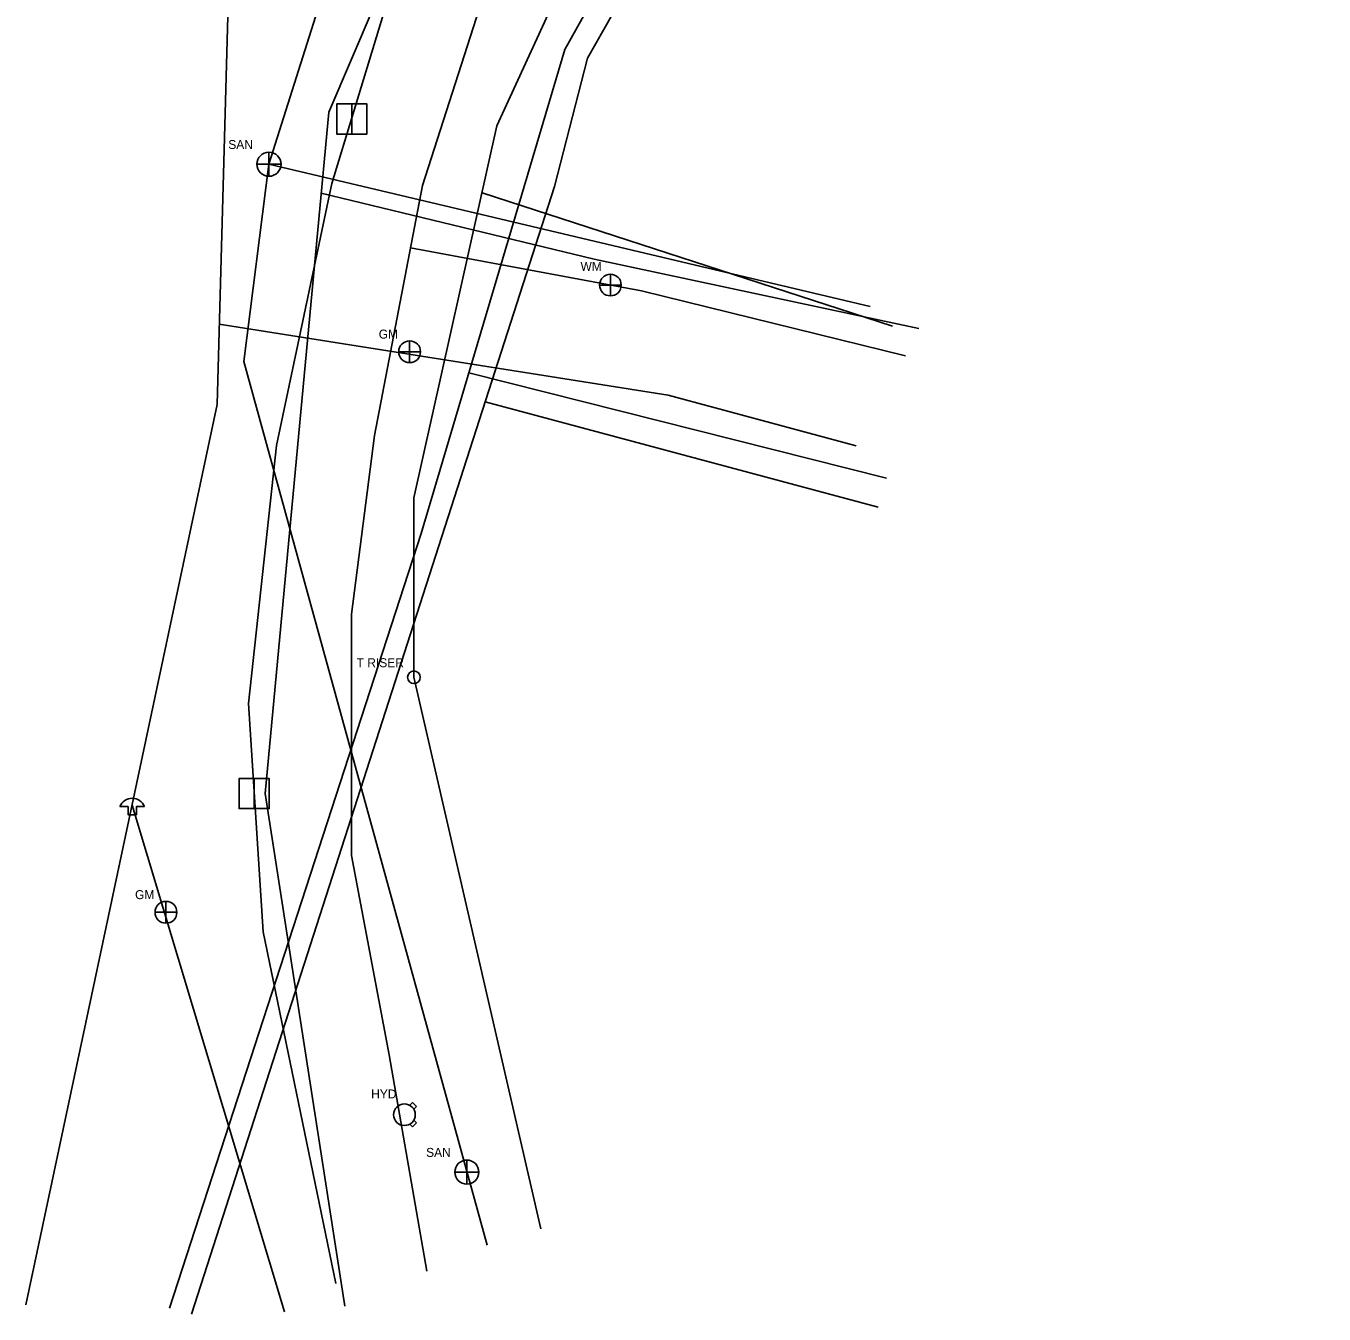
# Model space of a CAD drawing. Extents: x 551158 to 552108, y 1042267 to 1044064.
# Drawn here: x 551202 to 552108, y 1042267 to 1043165 of the extents above; entities that cross this region are included whole.
import ezdxf

# ---------------------------------------------------------------- set-up
doc = ezdxf.new("R2010")
doc.units = 0
for name, color, linetype in [('Common-Removals', 7, 'Continuous'), ('Utility-Cable', 7, 'Continuous'), ('Utility-Gas', 7, 'Continuous'), ('Utility-Pole', 7, 'Continuous'), ('Utility-Power', 7, 'Continuous'), ('Utility-Sanitary sewer', 7, 'Continuous'), ('Utility-Telephone', 7, 'Continuous'), ('Utility-Water', 7, 'Continuous')]:
    doc.layers.add(name, color=color, linetype=linetype)

msp = doc.modelspace()

# ---------------------------------------------------------------- linework, layer by layer
at = {"layer": 'Common-Removals'}
msp.add_line((551520.26, 1043049), (551806.58, 1042956.02), dxfattribs=at)
for points in [[(551418.21, 1042288.18), (551367.62, 1042533.64), (551357.31, 1042692.91), (551376.99, 1042872.8), (551415.4, 1043055.49), (551462.25, 1043209.14), (551535.32, 1043370.28), (551605.59, 1043490.2), (551705.83, 1043624.17), (551808.89, 1043763.77), (551899.77, 1043870.57), (552006.57, 1044001.74)], [(551561.23, 1042326.51), (551472.71, 1042711.13), (551472.71, 1042836.28), (551530.71, 1043095.75), (551631.44, 1043315.53), (551781.02, 1043556.68), (551942.8, 1043752.05), (552107.64, 1043938.25)]]:
    msp.add_lwpolyline(points, dxfattribs=at)
at = {"layer": 'Utility-Cable'}
msp.add_line((551510.99, 1042923.37), (551802.4, 1042849.99), dxfattribs=at)
msp.add_lwpolyline([(551302.24, 1042271), (551477.71, 1042811.45), (551578.06, 1043148.89), (551722.69, 1043407.88), (551880.78, 1043952.78), (551948.05, 1044063.78)], dxfattribs=at)
at = {"layer": 'Utility-Gas'}
for p, q in [((551469.82, 1042938.16), (551462.21, 1042938.16)), ((551469.77, 1042945.77), (551469.77, 1042938.16)), ((551469.77, 1042938.16), (551469.77, 1042938.16)), ((551469.77, 1042938.16), (551477.38, 1042938.16)), ((551469.77, 1042938.16), (551469.77, 1042930.6)), ((551276.1, 1042621.84), (551382.51, 1042268.41)), ((551299.79, 1042554.8), (551299.79, 1042547.19)), ((551299.84, 1042547.19), (551292.23, 1042547.19)), ((551299.79, 1042547.19), (551299.79, 1042547.19)), ((551299.79, 1042547.19), (551307.41, 1042547.19)), ((551299.79, 1042547.19), (551299.79, 1042539.63))]:
    msp.add_line(p, q, dxfattribs=at)
for points in [[(551883.28, 1044046.83), (551543.2, 1043513.97), (551342.83, 1043172.29), (551335.46, 1042901.45), (551202.12, 1042273.42)], [(551336.99, 1042957.33), (551650.09, 1042907.88), (551781.23, 1042872.53)], [(551267.69, 1042620.96), (551273.4, 1042620.96), (551273.4, 1042615.25), (551279.12, 1042615.25), (551279.12, 1042620.96), (551284.83, 1042620.96)]]:
    msp.add_lwpolyline(points, dxfattribs=at)
for centre in [(551469.77, 1042938.16), (551299.79, 1042547.19)]:
    msp.add_circle(centre, 7.61, dxfattribs=at)
for centre, radius, start, end in [((551469.77, 1042938.16), 7.61, 0.00229, 90.00084), ((551276.26, 1042617.4), 9.28, 22.56866, 157.43134), ((551299.79, 1042547.19), 7.61, 0.00229, 90.00084)]:
    msp.add_arc(centre, radius, start, end, dxfattribs=at)
at = {"layer": 'Utility-Pole'}
for points in [[(551418.98, 1043090.02), (551429.48, 1043090.02), (551429.48, 1043111.03), (551418.98, 1043111.03)], [(551418.98, 1043111.03), (551439.99, 1043111.03), (551439.99, 1043090.02), (551418.98, 1043090.02)], [(551350.8, 1042619.47), (551361.3, 1042619.47), (551361.3, 1042640.47), (551350.8, 1042640.47)], [(551350.8, 1042640.47), (551371.8, 1042640.47), (551371.8, 1042619.47), (551350.8, 1042619.47)]]:
    msp.add_lwpolyline(points, close=True, dxfattribs=at)
at = {"layer": 'Utility-Power'}
for points in [[(551985.8, 1044024.18), (551789, 1043787.2), (551589.43, 1043516.95), (551413.43, 1043105.33), (551369.08, 1042629.97), (551424.51, 1042272.41)], [(551408.16, 1043048.87), (551598.51, 1043002.84), (551824.9, 1042954.32)]]:
    msp.add_lwpolyline(points, dxfattribs=at)
at = {"layer": 'Utility-Sanitary sewer'}
for p, q in [((551371.64, 1043060.66), (551371.64, 1043077.36)), ((551363.34, 1043068.96), (551380.04, 1043068.96)), ((551791.14, 1042969.79), (551371.64, 1043069.06)), ((551371.64, 1043068.96), (551371.64, 1043068.96)), ((551509.66, 1042357.68), (551509.66, 1042374.39)), ((551501.36, 1042365.99), (551518.06, 1042365.99)), ((551509.66, 1042365.99), (551509.66, 1042365.99))]:
    msp.add_line(p, q, dxfattribs=at)
msp.add_lwpolyline([(551523.75, 1042314.92), (551354.03, 1042931.36), (551371.64, 1043069.06), (551430.88, 1043256.39), (551502.93, 1043406.9), (551815.16, 1043631.06), (552080.95, 1043954.5)], dxfattribs=at)
for centre in [(551371.64, 1043068.96), (551509.66, 1042365.98)]:
    msp.add_circle(centre, 8.4, dxfattribs=at)
at = {"layer": 'Utility-Telephone'}
msp.add_line((551522.43, 1042903.3), (551796.62, 1042829.74), dxfattribs=at)
msp.add_lwpolyline([(551317.6, 1042266.99), (551570.75, 1043053.4), (551593.86, 1043142.92), (551739.2, 1043398.96), (551898.99, 1043949.55), (551961.56, 1044055.43)], dxfattribs=at)
msp.add_circle((551472.71, 1042711.13), 4.42, dxfattribs=at)
at = {"layer": 'Utility-Water'}
for p, q in [((551609.79, 1042992.29), (551609.79, 1042977.19)), ((551602.29, 1042984.69), (551617.39, 1042984.69)), ((551609.79, 1042984.69), (551609.79, 1042984.69)), ((551469.85, 1042412.6), (551471.77, 1042414.54)), ((551471.77, 1042414.54), (551474.62, 1042411.7)), ((551466.11, 1042406.03), (551466.11, 1042406.03)), ((551474.62, 1042411.7), (551472.67, 1042409.77)), ((551471.77, 1042397.53), (551469.85, 1042399.46)), ((551474.62, 1042400.36), (551471.77, 1042397.53)), ((551472.67, 1042402.29), (551474.62, 1042400.36))]:
    msp.add_line(p, q, dxfattribs=at)
for points in [[(552051.51, 1043964.34), (551804.17, 1043658.21), (551747.41, 1043570.02), (551639.96, 1043397.7), (551520.34, 1043183.81), (551478.78, 1043054.06), (551445.33, 1042879.71), (551429.11, 1042755.03), (551429.11, 1042586.76), (551455.47, 1042447.88), (551481.82, 1042296.84)], [(551815.72, 1042935.23), (551631.48, 1042980.68), (551470.45, 1043010.65)]]:
    msp.add_lwpolyline(points, dxfattribs=at)
for centre in [(551609.79, 1042984.69), (551466.11, 1042406.03)]:
    msp.add_circle(centre, 7.56, dxfattribs=at)

# ---------------------------------------------------------------- texts
at = {"layer": 'Utility-Gas'}
for p in [(551448.21, 1042947.35), (551278.23, 1042556.38)]:
    msp.add_text('GM', height=6.251, dxfattribs=at).set_placement(p)
at = {"layer": 'Utility-Sanitary sewer'}
for p in [(551343.25, 1043079.57), (551481.27, 1042376.59)]:
    msp.add_text('SAN', height=6.251, dxfattribs=at).set_placement(p)
at = {"layer": 'Utility-Telephone'}
msp.add_text('T RISER', height=6.251, dxfattribs=at).set_placement((551432.78, 1042718.14))
at = {"layer": 'Utility-Water'}
for s, p in [('WM', (551588.97, 1042994.59)), ('HYD', (551442.93, 1042417.35))]:
    msp.add_text(s, height=6.251, dxfattribs=at).set_placement(p)

doc.saveas('drawing.dxf')
